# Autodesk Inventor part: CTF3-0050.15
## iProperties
Shininess: 64.0
Length Units: 11269
Angle Units: 11279
Time Units: 11290
Mass Units: 11283
Length Display Precision: 3
Angle Display Precision: 2
Compacted: True
Part Number: CTF3-0050.15
Document SubType Name: Modeling
Created: 2004-01
Designer: Lollo
Density: 0.0
Volumn: 0.0
Area: 0.0
PropertySet Name: Model Information
Control State: 0
Master: False
Checked Out: False
Author: Lollo
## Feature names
1. Estrusione1 [Extrusion]
2. Estrusione2 [Extrusion]
3. Foro1 [Hole]
4. Smusso1 [Chamfer]
5. Estrusione3 [Extrusion]
6. Smusso3 [Chamfer]
